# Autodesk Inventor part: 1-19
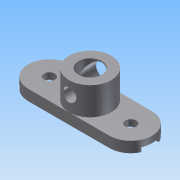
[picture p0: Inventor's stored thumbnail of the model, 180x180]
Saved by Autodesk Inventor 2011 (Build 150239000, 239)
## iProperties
Created: 2014-02
Part Number: 1-19
Document SubType Name: Modeling
Designer: Administrator
Density: 1 g/cm^3
Author: Administrator
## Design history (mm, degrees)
sketch "草图1"
  geometry: L1 (19, -9.946)-(-19, -9.946); L2 (-18.978, 9.946)-(19, 9.946); L3 (0, 0)-(0, 20.997); A1 r 9.946 centre (-19, 0) between (-18.978, 9.946) and (-19, -9.946); A2 r 9.946 centre (19, 0) between (19, -9.946) and (19, 9.946)
  constraints: 7 end point, 4 point on circle, 3 tangent, 2 centre point, 2 horizontal alignment, 1 perpendicular, 1 other
  dimensions: "d25" = 38 distance of A2.centre A1.centre
extrude "拉伸1" new body sketch "草图1" distance "d0" = 5; taper "d1" = 0 deg
sketch "草图3"
  geometry: C1 r 9.901 at (0, 0); 1 further point
  constraints: 1 centre point, 1 coincident
  dimensions: "d31" = 19.80287 diameter of C1
extrude "拉伸3" join sketch "草图3" distance "d4" = 13; taper "d5" = 0 deg
sketch "草图4"
  geometry: L1 (-19, 9.946)-(18.978, 9.946) reference; L2 (-28.051, -4.125)-(28.051, -4.125); L3 (28.125, 3.958)-(-28.125, 3.958); A1 r 9.946 centre (-19, 0) between (-19, 9.946) and (-19, -9.946) reference; A2 r 9.946 centre (19, 0) between (19, -9.946) and (18.978, 9.946) reference; 1 further point
  constraints: 4 end point, 4 point on circle, 2 parallel
extrude "拉伸4" cut sketch "草图4" distance "d6" = 2; taper "d7" = 0 deg
sketch "草图5"
  geometry: C1 r 9.901 at (0, 0) reference; C2 r 5.5 at (0, 0)
  constraints: 1 centre point, 1 coincident
  dimensions: "d26" = 11 diameter of C2
extrude "拉伸5" cut sketch "草图5" stored distance "d8" = 2; taper "d9" = 0 deg
hole "Hole1" diameter "d12" = 5; stored, may be unused: countersink angle "d16" = 90 deg, drill point angle "d18" = 118 deg; dims "d10" = 10, "d11" = 10, "d13" = 6, "d14" = 4, "d15" = 2, "d17" = 8
mirror "镜像1"
sketch "草图6"
  geometry: L1 (38, 5)-(0, 5) reference; C1 r 3 at (19, 12); 2 further points
  constraints: 1 centre point, 1 midpoint, 1 vertical alignment
  dimensions: "d28" = 7 distance from line of L1 C1.centre
extrude "拉伸6" cut sketch "草图6" stored distance "d20" = 2; taper "d21" = 0 deg
sketch "草图8"
  geometry: L1 (0, -5)-(37.978, -5) reference; 4 further points
  constraints: 1 midpoint, 1 vertical alignment
  dimensions: "d30" = 7 distance from line of point (18.989, -12) L1
hole "Hole2" sketch "草图8" at (18.989, -12) diameter "d32" = 11; stored, may be unused: countersink angle "d36" = 90 deg, drill point angle "d38" = 0 deg; dims "d33" = 6, "d34" = 4, "d35" = 2, "d37" = 9.9
node "实体1"
